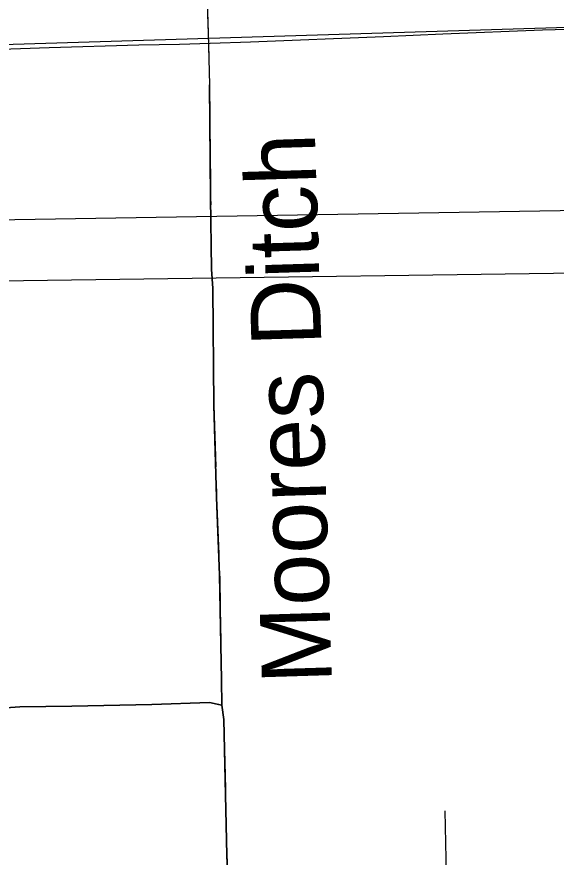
# Model space of a CAD drawing. Extents: x 646058 to 725608, y 1473014 to 1561048.
# Drawn here: x 655339 to 656968, y 1553140 to 1555679 of the extents above; entities that cross this region are included whole.
import ezdxf

# ---------------------------------------------------------------- set-up
doc = ezdxf.new("R2010")
doc.units = 0
doc.layers.add('Default', color=7, linetype='Continuous')

msp = doc.modelspace()

# ---------------------------------------------------------------- linework, layer by layer
at = {"layer": 'Default'}
for points in [[(653797.8, 1556987.9), (653873, 1556948.7), (653894.3, 1556920.9), (653946.6, 1556826.1), (654026.6, 1556713.3), (654043, 1556680.6), (654043, 1556630), (654077.3, 1556237.7), (654098.5, 1556191.9), (654150.8, 1556154.3), (654342, 1556102), (654363.3, 1556110.2), (654552.8, 1556195.2), (654590.4, 1556208.2), (654922.1, 1556223), (655771.9, 1556254), (655897.7, 1556255.6), (655896.1, 1556234.4), (655909.2, 1555889.9), (655917.3, 1555630), (655921.6, 1555474.2)], [(653919.1, 1556875.9), (653946.6, 1556826.1), (654026.6, 1556713.3), (654043, 1556680.6), (654043, 1556630), (654077.3, 1556237.7), (654098.5, 1556191.9), (654150.8, 1556154.3), (654342, 1556102), (654363.3, 1556110.2), (654552.8, 1556195.2), (654590.4, 1556208.2), (654922.1, 1556223), (655771.9, 1556254), (655897.7, 1556255.6), (655896.1, 1556234.4), (655909.2, 1555889.9), (655917.3, 1555630), (655921.6, 1555474.2)], [(655913.4, 1555754.8), (655916.5, 1555655.8)], [(655261.9, 1555594.5), (657888, 1555674.8)], [(653732.3, 1555515.5), (653800.2, 1555515), (654107.4, 1555532), (654344.2, 1555541.3), (654528.4, 1555548.2), (654865, 1555563.7), (655077, 1555572.2), (655262.7, 1555580.8), (655436.8, 1555586.2), (655707.7, 1555594.7), (655830.7, 1555596.2), (655923.6, 1555600.1), (656045, 1555604), (656446.7, 1555620.2), (656625.4, 1555628), (656926.4, 1555639.6), (657231.3, 1555648.1), (657507.6, 1555658.2), (657676.3, 1555663.6), (657882.9, 1555670.5)], [(653836.5, 1555517), (654107.4, 1555532), (654344.2, 1555541.3), (654528.4, 1555548.2), (654865, 1555563.7), (655077, 1555572.2), (655262.7, 1555580.8), (655436.8, 1555586.2), (655707.7, 1555594.7), (655830.7, 1555596.2), (655923.6, 1555600.1), (656045, 1555604), (656446.7, 1555620.2), (656625.4, 1555628), (656926.4, 1555639.6), (657231.3, 1555648.1), (657507.6, 1555658.2), (657676.3, 1555663.6), (657882.9, 1555670.5)], [(655916.5, 1555655.8), (655917.3, 1555630), (655919.4, 1555556.9)], [(655921.2, 1555490.9), (655921.6, 1555474.2)], [(655958.8, 1553599.2), (655957.5, 1553675.7), (655951.8, 1553993.3), (655942.7, 1554227.2), (655934.3, 1554506.1), (655930.8, 1554858.8), (655927.3, 1554917.1), (655924.5, 1555132.8), (655921.6, 1555474.2)], [(655921.6, 1555474.2), (655924.5, 1555132.8), (655927.3, 1554917.1), (655930.8, 1554858.8), (655934.3, 1554506.1), (655942.7, 1554227.2), (655951.8, 1553993.3), (655957.5, 1553675.7), (655958.8, 1553599.2)], [(655921.6, 1555474.2), (655922.5, 1555375.2)], [(655923, 1555309.2), (655924.5, 1555132.8), (655924.7, 1555111.2)], [(668379.5, 1555281.6), (649175.8, 1554963.8)], [(668379.5, 1555281.6), (649175.8, 1554963.8)], [(649175.8, 1554797.2), (668379.5, 1555063.1)], [(649175.8, 1554797.2), (668379.5, 1555063.1)], [(655925.6, 1555045.2), (655927.3, 1554917.1), (655930.8, 1554858.8), (655930.9, 1554847.3)], [(655931.5, 1554781.3), (655933.5, 1554583.3)], [(655934.2, 1554517.3), (655934.3, 1554506.1), (655939.9, 1554319.4)], [(655941.9, 1554253.5), (655942.7, 1554227.2), (655949.4, 1554055.6)], [(655951.9, 1553989.6), (655953.7, 1553890.7)], [(655953.7, 1553890.7), (655955.4, 1553791.7)], [(655956.6, 1553725.7), (655957.5, 1553675.7), (655958.8, 1553599.2)], [(656022.1, 1551653.3), (656016.5, 1551688.2), (656011.1, 1551986.3), (655995, 1552500.7), (655983, 1552926.4), (655973.6, 1553146.6), (655964.2, 1553556.2), (655958.8, 1553599.2), (655921.2, 1553607.3), (655746.6, 1553601.9), (655505, 1553596.5), (655347.9, 1553593.9), (655247.2, 1553587.1), (654926.3, 1553576.4), (654515.4, 1553565.6), (654193.2, 1553554.9), (654002.5, 1553549.5)], [(654002.5, 1553549.5), (654193.2, 1553554.9), (654515.4, 1553565.6), (654926.3, 1553576.4), (655247.2, 1553587.1), (655347.9, 1553593.9), (655505, 1553596.5), (655746.6, 1553601.9), (655921.2, 1553607.3), (655958.8, 1553599.2), (655964.2, 1553556.2), (655973.6, 1553146.6), (655976.4, 1553079.7)], [(655222.9, 1553586.3), (655247.2, 1553587.1), (655347.9, 1553593.9), (655420.7, 1553595.1)], [(655486.7, 1553596.2), (655505, 1553596.5), (655585.7, 1553598.3)], [(655585.7, 1553598.3), (655684.6, 1553600.5)], [(655750.6, 1553602), (655921.2, 1553607.3), (655947.9, 1553601.5)], [(655964.4, 1553544.7), (655969, 1553346.7)], [(655970.5, 1553280.7), (655973.6, 1553146.6), (655976.3, 1553082.8)], [(656631.6, 1553280.3), (656638.2, 1552990.3)]]:
    msp.add_lwpolyline(points, dxfattribs=at)

# ---------------------------------------------------------------- texts
msp.add_text('Moores Ditch', height=211.2, rotation=91.7816, dxfattribs=at).set_placement((656291, 1553667.1))

doc.saveas('drawing.dxf')
